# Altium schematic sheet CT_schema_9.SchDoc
size 386 x 278 mm
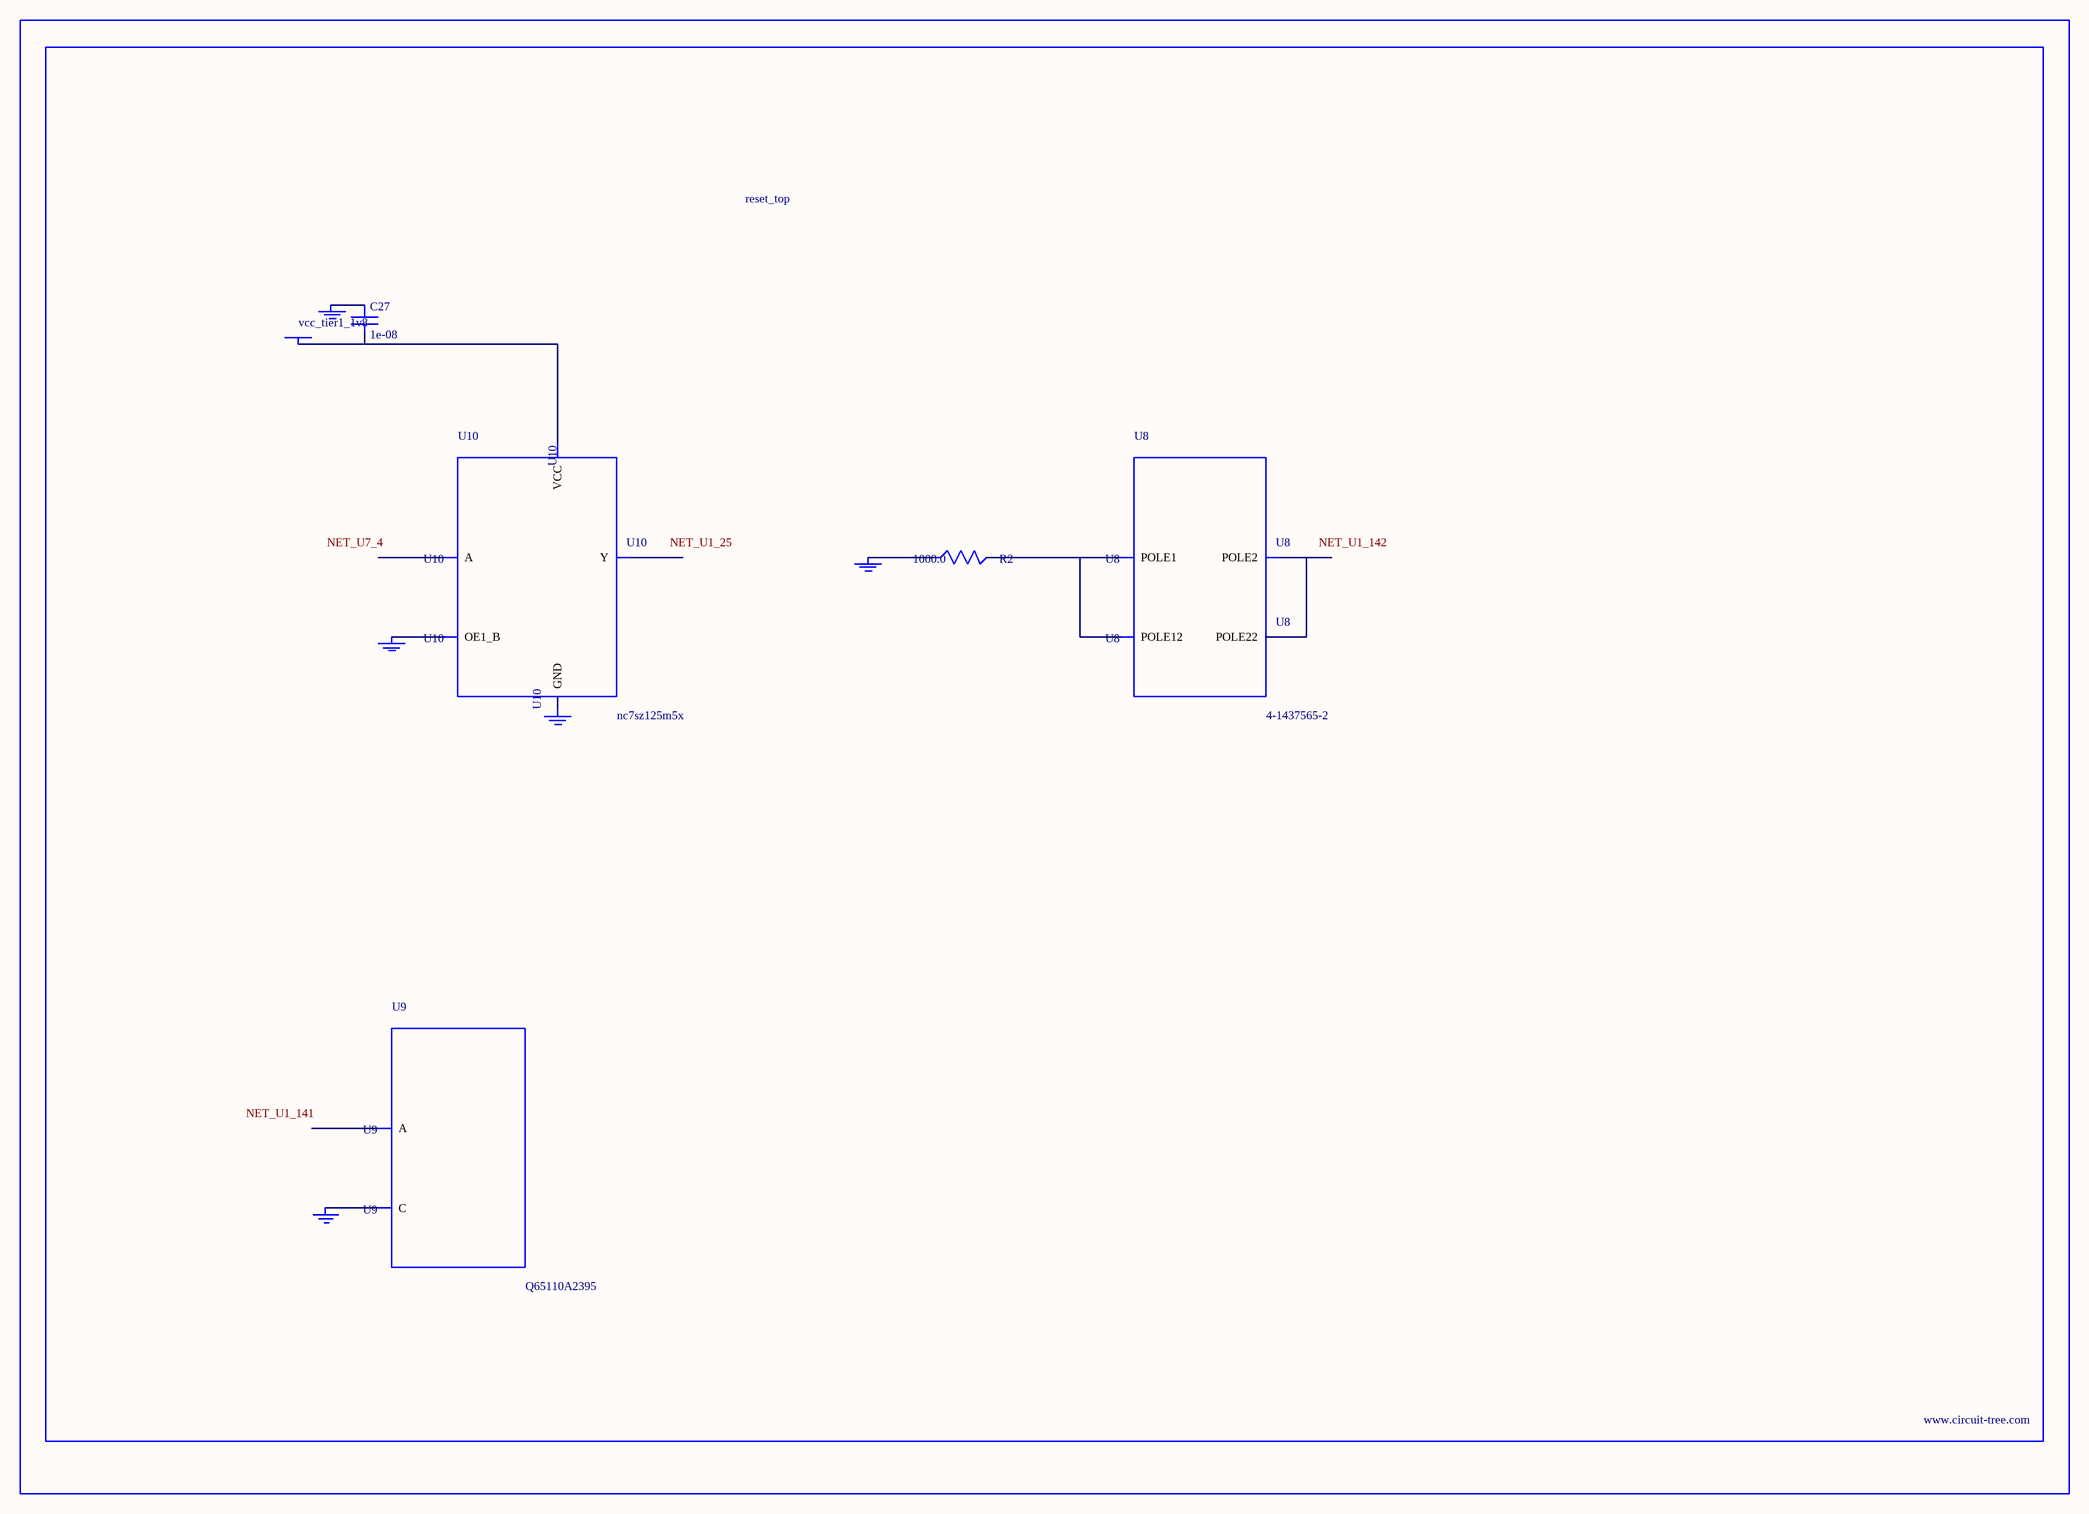
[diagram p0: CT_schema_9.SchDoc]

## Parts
BORDER8  (no value)
C27  1e-08  [C0402]
GND_INSTANCE_8_0  (no value)
GND_INSTANCE_8_1  (no value)
GND_INSTANCE_8_2  (no value)
GND_INSTANCE_8_3  (no value)
GND_INSTANCE_8_4  (no value)
POWER_INSTANCE_8_0  vcc_tier1_1v8
R2  1000.0  [R0603]
U8  4-1437565-2  [SW_4-1437565-2]
U9  Q65110A2395  [LGM67K-G1J2-24-Z]
U10  nc7sz125m5x  [NC7SZ125M5X]

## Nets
NetC27_1: C27.1 GND_INSTANCE_8_2.0(GND)
NetC27_2: C27.2 POWER_INSTANCE_8_0.0(PWR) U10.5(VCC)
NetGND_INSTANCE_8_0_0: GND_INSTANCE_8_0.0(GND) R2.1
NetGND_INSTANCE_8_1_0: GND_INSTANCE_8_1.0(GND) U9.C
NetGND_INSTANCE_8_3_0: GND_INSTANCE_8_3.0(GND) U10.1(OE1_B)
NetGND_INSTANCE_8_4_0: GND_INSTANCE_8_4.0(GND) U10.3(GND)
NetR2_2: R2.2 U8.1(POLE1) U8.2(POLE12)
NetU8_3: U8.3(POLE2) U8.4(POLE22)

Not connected (* = marked no-connect by the designer): U9 A; U10 2(A) 4(Y)

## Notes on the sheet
- Labels drawn without touching a wire or pin: NET_U1_25, NET_U1_141, NET_U1_142, NET_U7_4

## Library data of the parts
BORDER8 = BORDER_PAGE8
C27 = C0402C103K3RAC
GND_INSTANCE_8_0-GND_INSTANCE_8_4 = GND
POWER_INSTANCE_8_0 = PWR
R2 = RC0603JR-071KL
